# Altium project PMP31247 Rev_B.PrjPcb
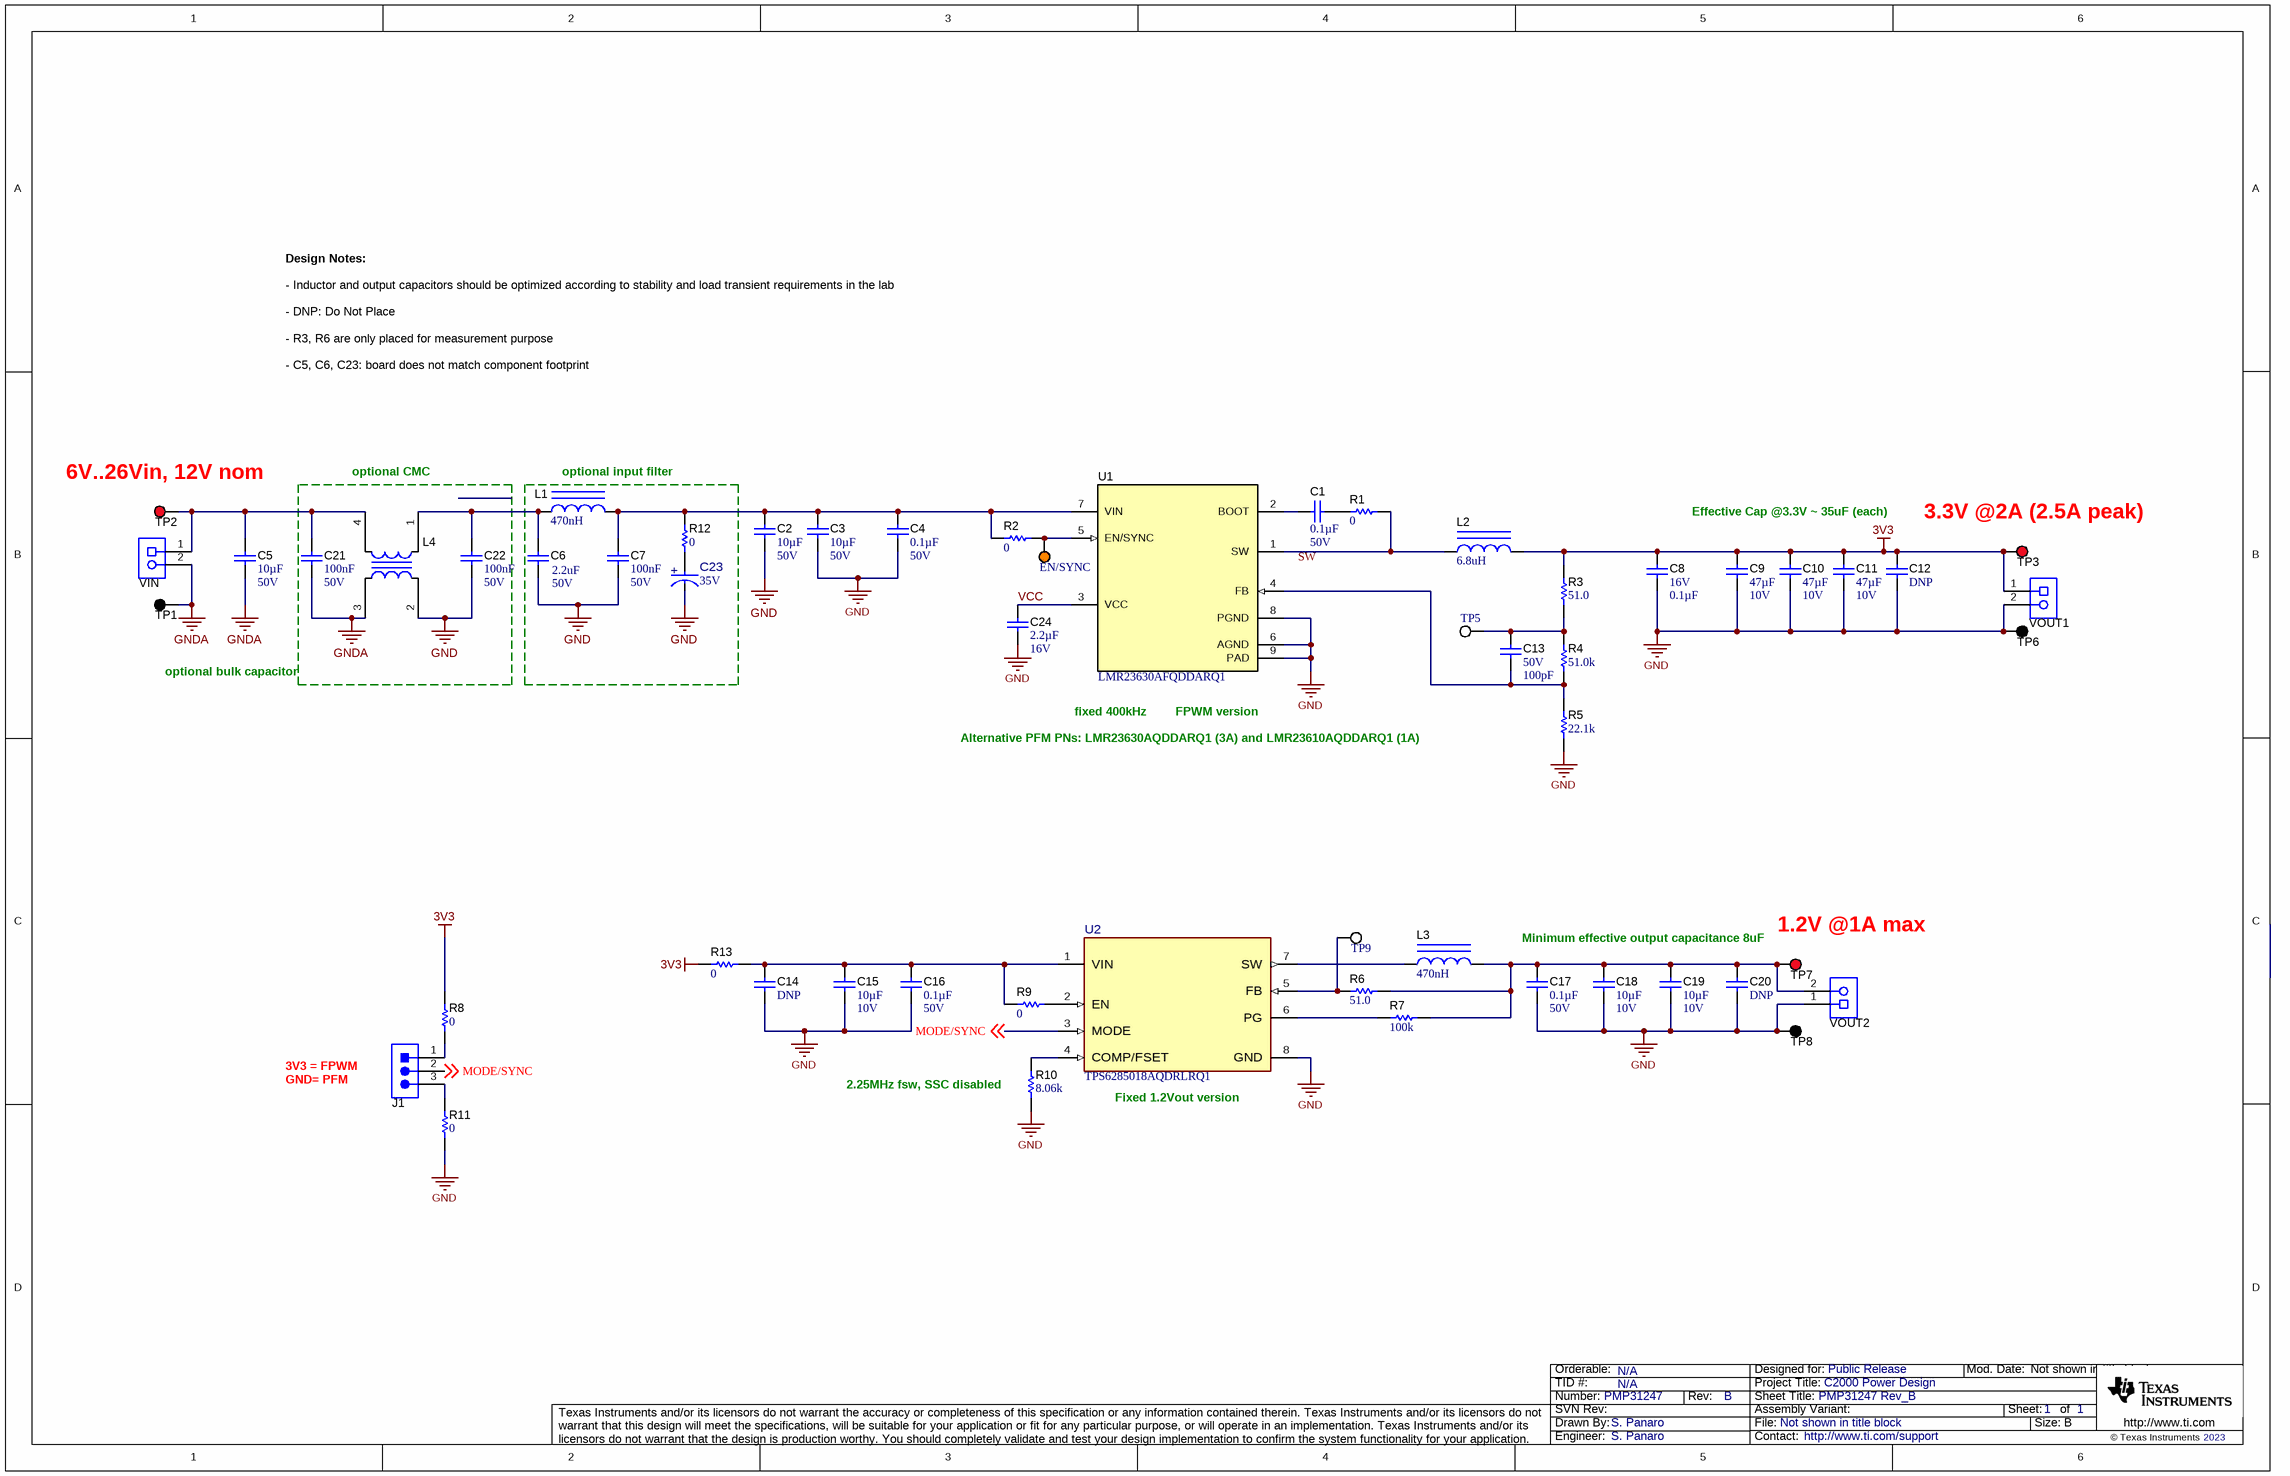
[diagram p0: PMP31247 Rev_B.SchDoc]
TID: N/A; TechSupport: http://www.ti.com/support; SCH_Rev: B; PRJ_Title: C2000 Power Design; PRJ_Number: PMP31247; PRJ_Engineer: S. Panaro; PRJ_Customer: Public Release; Orderable: N/A; CopyrightYear: 2023
1 sheet, 56 parts. Net scope: global (net labels, ports and power ports of the same name join across sheets).
Board file: PMP31247 Rev_B.PcbDoc

## Sheet PMP31247 Rev_B.SchDoc: PMP31247 Rev_B
size 431 x 279 mm; Date: Not shown in title block; ApprovedBy: Not shown in title block; CheckedBy: Not shown in title block; Author: Not shown in title block; CompanyName: Not shown in title block; DrawnBy: S. Panaro; Engineer: S. Panaro; Organization: Not shown in title block; Address1: Not shown in title block; Address2: Not shown in title block; Address3: Not shown in title block; Address4: Not shown in title block; DocumentNumber: 1; Revision: Use project parameter SCH_Rev; SheetNumber: 1; SheetTotal: 1; PageSetup: Record=PageOptions¦CenterHorizontal=True¦CenterVertical=True¦PrintScale=1.00¦XCorrection=1.00¦YCorrection=1.00¦PrintKind=0¦BorderSize=5000000¦LeftOffset=0¦BottomOffset=0¦Orientation=2¦PaperLength=1000¦PaperWidth=1000¦Scale=100¦PaperSource=15¦PrintQuality=600¦MediaType=1¦DitherType=10¦PaperKind=Letter¦PrintScaleMode=1; EVM_orderable: N/A

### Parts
C1  ValueDisplayed: 0.1µF  VDC_V: 50V  [0402]  (hidden comment: CGA2B3X7R1H104K050BD)
C2  ValueDisplayed: 10µF  VDC_V: 50V  [1206]  (hidden comment: CGA5L1X7R1H106K160AE)
C3  ValueDisplayed: 10µF  VDC_V: 50V  [1206]  (hidden comment: CGA5L1X7R1H106K160AE)
C4  ValueDisplayed: 0.1µF  VDC_V: 50V  [0402]  (hidden comment: CGA2B3X7R1H104K050BD)
C5  ValueDisplayed: 10µF  VDC_V: 50V  [1206]  (hidden comment: CGA5L1X7R1H106K160AE)
C6  VDC_V: 50V  ValueDisplayed: 2.2uF  [1206_180]  (hidden comment: GCM31CR71H225KA55L)
C7  Cap_F: 100nF  VDC_V: 50V  [0603]  (hidden comment: C0603C104K5RACAUTO)
C8  VDC_V: 16V  ValueDisplayed: 0.1µF  [0402]  (hidden comment: GCM155R71C104JA55D)
C9  Cap_F: 47µF  VDC_V: 10V  [1210_270]  (hidden comment: GRM32ED71A476ME15L)
C10  Cap_F: 47µF  VDC_V: 10V  [1210_270]  (hidden comment: GRM32ED71A476ME15L)
C11  Cap_F: 47µF  VDC_V: 10V  [1210_270]  (hidden comment: GRM32ED71A476ME15L)
C12  Cap_F: DNP  [1210_270]  (hidden comment: GRM32ED71A476ME15L)
C13  VDC_V: 50V  ValueDisplayed: 100pF  [0603]  (hidden comment: 06035A101JAT2A)
C14  Cap_F: DNP  [0603]  (hidden comment: GRM188Z71A106MA73D)
C15  Cap_F: 10µF  VDC_V: 10V  [0603]  (hidden comment: GRM188Z71A106MA73D)
C16  ValueDisplayed: 0.1µF  VDC_V: 50V  [0402]  (hidden comment: CGA2B3X7R1H104K050BD)
C17  ValueDisplayed: 0.1µF  VDC_V: 50V  [0402]  (hidden comment: CGA2B3X7R1H104K050BD)
C18  Cap_F: 10µF  VDC_V: 10V  [0603]  (hidden comment: GRM188Z71A106MA73D)
C19  Cap_F: 10µF  VDC_V: 10V  [0603]  (hidden comment: GRM188Z71A106MA73D)
C20  Cap_F: DNP  [0603]  (hidden comment: GRM188Z71A106MA73D)
C21  Cap_F: 100nF  VDC_V: 50V  [0603]  (hidden comment: C0603C104K5RACAUTO)
C22  Cap_F: 100nF  VDC_V: 50V  [0603]  (hidden comment: C0603C104K5RACAUTO)
C23  VDC_V: 35V  [FP-EEH-ZK1V101XP_RADIAL-MFG]  (hidden comment: EEH-ZK1V390UR)
C24  Cap_F: 2.2µF  VDC_V: 16V  [0603]  (hidden comment: EMK107BB7225KA-T)
EN/SYNC  5003  [Keystone5003]  (value not drawn)
J1  61300311121  [WURTH_61300311121]  (value not drawn)
L1  ValueDisplayed: 470nH  [SRN2010TA]  (hidden comment: SRN2010TA-R47Y)
L2  ValueDisplayed: 6.8uH  [WE-PD_1260]  (hidden comment: 744771006)
L3  ValueDisplayed: 470nH  [DFE252012P]  (hidden comment: DFE252012PD-R47M)
L4  ACM9070-701-2PL-TL01  [TDK_ACM9070]  (value not drawn)
R1  ValueDisplayed: 0  [0402]  (hidden comment: CRCW04020000Z0ED)
R2  ValueDisplayed: 0  [0603]  (hidden comment: CRCW06030000Z0EA)
R3  ValueDisplayed: 51.0  [0603]  (hidden comment: RC0603FR-0751RL)
R4  ValueDisplayed: 51.0k  [0603]  (hidden comment: RC0603FR-0751KL)
R5  ValueDisplayed: 22.1k  [0603]  (hidden comment: CRCW060322K1FKEA)
R6  ValueDisplayed: 51.0  [0603]  (hidden comment: RC0603FR-0751RL)
R7  ValueDisplayed: 100k  [0603]  (hidden comment: CRCW0603100KFKEA)
R8  ValueDisplayed: 0  [0603]  (hidden comment: CRCW06030000Z0EA)
R9  ValueDisplayed: 0  [0603]  (hidden comment: CRCW06030000Z0EA)
R10  ValueDisplayed: 8.06k  [0603]  (hidden comment: CRCW06038K06FKEA)
R11  ValueDisplayed: 0  [0603]  (hidden comment: CRCW06030000Z0EA)
R12  ValueDisplayed: 0  [0603]  (hidden comment: CRCW06030000Z0EA)
R13  ValueDisplayed: 0  [0603]  (hidden comment: CRCW06030000Z0EA)
TP1  5011  [Keystone5011]  (value not drawn)
TP2  5010  [Keystone5010]  (value not drawn)
TP3  5010  [Keystone5010]  (value not drawn)
TP5  5012  [Keystone5012]  (value not drawn)
TP6  5011  [Keystone5011]  (value not drawn)
TP7  5010  [Keystone5010]  (value not drawn)
TP8  5011  [Keystone5011]  (value not drawn)
TP9  5012  [Keystone5012]  (value not drawn)
U1  LMR23630AFQDDARQ1  [DDA0008E_L]
U2  TPS6285018AQDRLRQ1  [DRL0008A-MFG]
VIN  ED120/2DS  [On-Shore_ED120_2DS]  (value not drawn)
VOUT1  ED120/2DS  [On-Shore_ED120_2DS]  (value not drawn)
VOUT2  ED120/2DS  [On-Shore_ED120_2DS]  (value not drawn)

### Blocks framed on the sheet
optional CMC: C21 C22 L4
optional input filter: C6 C7 C23 L1 R12

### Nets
3V3: C8.1 C9.1 C10.1 C11.1 C12.1 L2.2 R3.2 R8.2 R13.1 TP3.1 VOUT1.1
GND: C2.2 C3.2 C4.2 C6.2 C7.2 C8.2 C9.2 C10.2 C11.2 C12.2 C14.2 C15.2 C16.2 C17.2 C18.2 C19.2 C20.2 C22.2 C23.1(CATHODE) C24.2 L4.2 R5.1 R10.1 R11.1 TP6.1 TP8.1 U1.6(AGND) U1.8(PGND) U1.9(PAD) U2.8(GND) VOUT1.2 VOUT2.1
GNDA: C5.2 C21.2 L4.3 TP1.1 VIN.2
MODE/SYNC: J1.2 U2.3(MODE) ; off-sheet MODE/SYNC
VCC: C24.1 U1.3(VCC)
NetC1_1: C1.1 U1.2(BOOT)
NetC1_2: C1.2 R1.2
NetC2_1: C2.1 C3.1 C4.1 C7.1 L1.2 R2.1 R12.2 U1.7(VIN)
NetC5_1: C5.1 C21.1 L4.4 TP2.1 VIN.1
NetC6_1: C6.1 C22.1 L1.1 L4.1
NetC13_1: C13.1 R3.1 R4.2 TP5.1
NetC13_2: C13.2 R4.1 R5.2 U1.4(FB)
NetC14_1: C14.1 C15.1 C16.1 R9.1 R13.2 U2.1(VIN)
NetC17_1: C17.1 C18.1 C19.1 C20.1 L3.2 R6.1 R7.2 TP7.1 VOUT2.2
NetC23_2: C23.2(ANODE) R12.1
NetEN/SYNC_1: EN/SYNC.1 R2.2 U1.5(EN/SYNC)
NetJ1_1: J1.1 R8.1
NetJ1_3: J1.3 R11.2
NetL2_1: L2.1 R1.1 U1.1(SW)
NetL3_1: L3.1 U2.7(SW)
NetR6_2: R6.2 TP9.1 U2.5(FB)
NetR7_1: R7.1 U2.6(PG)
NetR9_2: R9.2 U2.2(EN)
NetR10_2: R10.2 U2.4(COMP/FSET)

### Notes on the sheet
- Design Notes:
- - Inductor and output capacitors should be optimized according to stability and load transient requirements in the lab
- - DNP: Do Not Place
- - R3, R6 are only placed for measurement purpose
- - C5, C6, C23: board does not match component footprint
- (near TP2) 6V..26Vin, 12V nom
- Effective Cap @3.3V ~ 35uF (each)
- (near TP3) 3.3V @2A (2.5A peak)
- optional bulk capacitor
- (near U1) fixed 400kHz
- Alternative PFM PNs: LMR23630AQDDARQ1 (3A) and LMR23610AQDDARQ1 (1A)
- (near U1) FPWM version
- Minimum effective output capacitance 8uF
- (near TP7) 1.2V @1A max
- (near J1) 3V3 = FPWM                                                                                                             GND= PFM
- (near R10) 2.25MHz fsw, SSC disabled
- (near U2) Fixed 1.2Vout version
- Labels drawn without touching a wire or pin: SW

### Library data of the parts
C1 C4 C16 C17 = CMP-0084548-1: CAP, CERM, 0.1 µF, 50 V,+/- 10%, X7R, AEC-Q200 Grade 1, 0402; Manufacturer: TDK; SizeZ_mm: 0.6; TaMax_C: 125°C; Cap_F: 100nF; Polarized: N; SizeX_mm: 1; Value: 0.1uF; AEC Category: Q200; TaMin_C: -55°C; SizeArea_mm2: 0.5; SizeAreaWB_mm2: 3; U/M: EA; AEC Qualified: Y
C2 C3 C5 = CMP-0860898-1: CAP, CERM, 10 µF, 50 V,+/- 10%, X7R, AEC-Q200 Grade 1, 1206; Manufacturer: TDK; SizeY_mm: 1.6; AEC Category: Q200; U/M: EA; Polarized: N; TaMin_C: -55°C; TaMax_C: 125°C; SizeX_mm: 3.2; AEC Qualified: Y; SizeZ_mm: 1.35; Value: 10uF; SizeArea_mm2: 5.12; SizeAreaWB_mm2: 10.92; AEC Grade: 1
C6 = CMP-0008814-2: CAP, CERM, 2.2 uF, 50 V, +/- 10%, X7R, AEC-Q200 Grade 1, 1206; Manufacturer: MuRata; TaMin_C: -55°C; Polarized: N; SizeAreaWB_mm2: 10.92; Value1: Unknown; U/M: EA; Value: 2.2uF; TaMax_C: 125°C; SizeZ_mm: 1.8; SizeX_mm: 3.2; SizeY_mm: 1.6; Cap_Case: 1206; SizeArea_mm2: 5.12; AEC Qualified: Y; Cap_F: 2.2µF; AEC Grade: 1; AEC Category: Q200
C7 C21 C22 = CMP-0079602-1: CAP, CERM, 0.1 µF, 50 V,+/- 10%, X7R, AEC-Q200 Grade 1, 0603; Manufacturer: Kemet; TaMin_C: -55°C; Polarized: N; SizeAreaWB_mm2: 4.68; U/M: EA; Value: 0.1uF; TaMax_C: 125°C; SizeZ_mm: 1; SizeX_mm: 1.6; SizeY_mm: 0.8; SizeArea_mm2: 1.28; AEC Qualified: Y; AEC Category: Q200; ValueDisplayed: 0.1µF
C8 = CMP-0080702-1: CAP, CERM, 0.1 µF, 16 V,+/- 5%, X7R, AEC-Q200 Grade 1, 0402; Manufacturer: MuRata; Cap_F: 100nF; SizeAreaWB_mm2: 3; SizeArea_mm2: 0.5; AEC Qualified: Y; AEC Category: Q200; Value: 0.1uF; TaMax_C: 125°C; SizeZ_mm: 0.6; AEC Grade: 1; Polarized: N; TaMin_C: -55°C; U/M: EA
C9-C12 = CMP-0086480-2: 47µF ±20% 10V Ceramic Capacitor X7T 1210 (3225 Metric); Manufacturer: Murata; AEC Qualified: No; SizeZ_mm: 2.7mm; TempCo: +22-33%
C13 = CMP-0006763-4: CAP, CERM, 100 pF, 50 V, +/- 5%, C0G/NP0, 0603; Manufacturer: AVX; TaMin_C: -55°C; ESR_ohm: 0.119; Polarized: N; SizeAreaWB_mm2: 4.68; Value1: 0.119 ohm; U/M: EA; Value: 100pF; TaMax_C: 125°C; SizeZ_mm: 1; SizeX_mm: 1.6; SizeY_mm: 0.8; SizeArea_mm2: 1.28; AEC Category: Q200
C14 C20 = CMP-0007497-5: CAP, CERM, 10 uF, 10 V, +/- 20%, X7R, 0603; Manufacturer: MuRata; TaMin_C: -55°C; Polarized: N; SizeAreaWB_mm2: 4.68; Value1: Unknown; U/M: EA; Value: 10uF; TaMax_C: 125°C; SizeZ_mm: 1; SizeX_mm: 1.6; SizeY_mm: 0.8; Value2: 10V; SizeArea_mm2: 1.28; AEC Category: Q200
C15 C18 C19 = CMP-0007497-5: CAP, CERM, 10 uF, 10 V, +/- 20%, X7R, 0603; Manufacturer: MuRata; TaMin_C: -55°C; Polarized: N; SizeAreaWB_mm2: 4.68; Value1: Unknown; U/M: EA; Value: 10uF; TaMax_C: 125°C; SizeZ_mm: 1; SizeX_mm: 1.6; SizeY_mm: 0.8; SizeArea_mm2: 1.28; AEC Category: Q200
C23 = CMP-0097026-1: 39 µF 35 V Aluminum - Polymer Capacitors Radial, Can - SMD 100mOhm 4000 Hrs @ 125°C; Manufacturer: Panasonic; Cap_F: 39µF; AEC Qualified: Yes; Life: 4000Hours; Value: 39µF; Tolerance_%: 20%
C24 = CMP-0007121-4: CAP, CERM, 2.2 uF, 16 V, +/- 10%, X7R, 0603; Manufacturer: Taiyo Yuden; TaMin_C: -55°C; Polarized: N; SizeAreaWB_mm2: 4.68; Value1: Unknown; U/M: EA; Value: 2.2uF; TaMax_C: 125°C; SizeZ_mm: 1; SizeX_mm: 1.6; SizeY_mm: 0.8; SizeArea_mm2: 1.28; AEC Category: Q200
EN/SYNC = CMP-0055140-2: Test Point, Miniature, Orange, TH; Manufacturer: Keystone Electronics; Green_Lifecycle: Active; ContactFinish: Silver; CNHeader: FALSE; CT: TRUE; Green_REACh: Passed
J1 = CMP-0054796-2: Header, 2.54 mm, 3x1, Gold, TH; Manufacturer: Wurth Elektronik; Pitch_mm: 2.54; Green_Lifecycle: Active; Cert_UL: Y; Shrouded: N; Green_REACh: Passed; Gender: Male; Row_Count: 1
L1 = CMP-0056734-1: Inductor, Shielded, Ferrite, 470 nH, 2.35 A, 0.0528 ohm, AEC-Q200 Grade 1, SMD; Manufacturer: Bourns; Isat: 2.7A @ 30% inductance drop; Irms: 2.35A @ 40C rise; Green_Lifecycle: Active; SizeAreaWB_mm2: 7.8; DCR_ohm: 52.8m; Green_REACh: Passed; Value: 470nH; Imax_A: 2.35A; SizeZ_mm: 1; SizeX_mm: 2; SizeY_mm: 1.6; SizeArea_mm2: 3.2; AEC Qualified: Y; AEC Category: Q200
L2 = CMP-0064211-1: Inductor, Shielded Drum Core, Metal Composite, 6.8 uH, 5.6 A, 0.014 ohm, SMD; Manufacturer: Wurth Elektronik; Isat: 6A @ 10% inductance drop; Irms: 5.6A @ 40C rise; Green_Lifecycle: Active; SizeAreaWB_mm2: 196; DCR_ohm: 14m; Green_REACh: Passed; Value: 6.8uH; Imax_A: 5.6A; SizeZ_mm: 6; SizeX_mm: 12; SizeArea_mm2: 144; Ind_H: 6.8µH; AEC Category: Q200
L3 = CMP-0058944-1: Inductor, Shielded, 470 nH, 4.7 A, 0.021 ohm, SMD; Manufacturer: MuRata Toko; Isat: 6.1A @ 30% inductance drop; Irms: 4.7A @ 40C rise; SizeAreaWB_mm2: 10.5; DCR_ohm: 21m; Value: 470nH; Imax_A: 4.7A; SizeZ_mm: 1.2; SizeX_mm: 2.5; SizeY_mm: 2; SizeArea_mm2: 5; AEC Category: Q200
L4 = CMP-0013076-3: Coupled inductor, 5 A, 0.01 ohm, SMD; Manufacturer: TDK; DCR_ohm: 10m
R1 = CMP-0026822-1: RES, 0, 5%, 0.063 W, 0402; Manufacturer: Vishay-Dale; Power_W: 63mW; TempCo: 200 ppm/C; Value_Code: 0000; U/M: EA; Value: 0; EIA_Code: E24; SizeX_mm: 1; SizeY_mm: 0.5; SizeZ_mm: 0.6; Value2: 0.063W; VDC_V: 50V; AEC Category: Q200
R2 R8 R9 R11 R13 = CMP-0025697-2: RES, 0, 5%, 0.1 W, 0603; Manufacturer: Vishay-Dale; Power_W: 100mW; TempCo: 200 ppm/C; Value_Code: 0000; U/M: EA; Value: 0; EIA_Code: E24; SizeX_mm: 1.6; SizeY_mm: 0.8; SizeZ_mm: 1; Value2: 0.1W; SizeArea_mm2: 1.28; VDC_V: 75V; AEC Category: Q200
R3 R6 = CMP-0023169-5: RES, 51.0, 1%, 0.1 W, 0603; Manufacturer: Yageo; Power_W: 100mW; TempCo: 100 ppm/C; Value_Code: 51R0; Value: 51.0; Res_ohm: 51; SizeX_mm: 1.6; SizeY_mm: 0.8; SizeZ_mm: 1; Value2: 0.1W; SizeArea_mm2: 1.28; AEC Qualified: N; VDC_V: 75V; AEC Category: Q200; SizeAreaWB_mm2: 4.68
R4 = CMP-0023167-5: RES, 51.0 k, 1%, 0.1 W, 0603; Manufacturer: Yageo; Power_W: 100mW; TempCo: 100 ppm/C; Value_Code: 51k0; Value: 51.0k; Res_ohm: 51k; SizeX_mm: 1.6; SizeY_mm: 0.8; SizeZ_mm: 1; Value2: 0.1W; SizeArea_mm2: 1.28; AEC Qualified: N; VDC_V: 75V; AEC Category: Q200; SizeAreaWB_mm2: 4.68
R5 = CMP-0022220-4: RES, 22.1 k, 1%, 0.1 W, AEC-Q200 Grade 0, 0603; Manufacturer: Vishay-Dale; Power_W: 100mW; TempCo: 100 ppm/C; Value_Code: 22k1; Value: 22.1k; EIA_Code: E96; SizeX_mm: 1.6; SizeY_mm: 0.8; SizeZ_mm: 1; Value2: 0.1W; SizeArea_mm2: 1.28; AEC Qualified: Y; VDC_V: 75V; AEC Category: Q200; AEC Grade: 0
R7 = CMP-0021990-4: RES, 100 k, 1%, 0.1 W, AEC-Q200 Grade 0, 0603; Manufacturer: Vishay-Dale; Power_W: 100mW; TempCo: 100 ppm/C; Value: 100k; EIA_Code: E96; SizeX_mm: 1.6; SizeY_mm: 0.8; SizeZ_mm: 1; Value2: 0.1W; SizeArea_mm2: 1.28; AEC Qualified: Y; VDC_V: 75V; AEC Category: Q200; AEC Grade: 0
R10 = CMP-0022634-4: RES, 8.06 k, 1%, 0.1 W, AEC-Q200 Grade 0, 0603; Manufacturer: Vishay-Dale; Power_W: 100mW; TempCo: 100 ppm/C; Value_Code: 8k06; Value: 8.06k; EIA_Code: E96; SizeX_mm: 1.6; SizeY_mm: 0.8; SizeZ_mm: 1; Value2: 0.1W; SizeArea_mm2: 1.28; AEC Qualified: Y; VDC_V: 75V; AEC Category: Q200; AEC Grade: 0
R12 = CMP-0025697-4: RES, 0, 5%, 0.1 W, AEC-Q200 Grade 0, 0603; Manufacturer: Vishay-Dale; Power_W: 100mW; TempCo: 200 ppm/C; Value_Code: 0000; Value: 0; EIA_Code: E24; SizeX_mm: 1.6; SizeY_mm: 0.8; SizeZ_mm: 1; Value2: 0.1W; SizeArea_mm2: 1.28; AEC Qualified: Y; VDC_V: 75V; AEC Category: Q200
TP1 TP6 TP8 = CMP-0055148-1: Test Point, Multipurpose, Black, TH; Manufacturer: Keystone; CNHeader: FALSE; Green_Lifecycle: Active; Green_REACh: Passed; ContactFinish: Silver; CT: TRUE
TP2 TP3 TP7 = CMP-0055147-1: Test Point, Multipurpose, Red, TH; Manufacturer: Keystone; CNHeader: FALSE; Green_Lifecycle: Active; Green_REACh: Passed; ContactFinish: Silver; CT: TRUE
TP5 TP9 = CMP-0055149-2: Test Point, Multipurpose, White, TH; Manufacturer: Keystone Electronics; ContactFinish: Silver; CT: TRUE; CNHeader: FALSE; Green_Lifecycle: Active; Green_REACh: Passed
U1 = CMP-0013268-3: SIMPLE SWITCHER, 36V, 3A Synchronous Step-Down Converter, DDA0008E (SOIC-8); Alternate PartNumber: LMR23630AFQDDAQ1; Manufacturer: Texas Instruments; SizeZ_mm: 1.7; SizeX_mm: 5; SizeY_mm: 6.2; SizeArea_mm2: 31; CompType: IC; U/M: EA; SizeAreaWB_mm2: 57.4
U2 = CMP-0092216-2: 1.2V fixed voltage Step-Down Converter; Manufacturer: Texas Instruments; Standoff Height: 0mm; TJmax_C: +150°C; SizeZ_mm: 0.6mm; Switching Frequency: 1.8-4MHz; Min Supply Voltage: 2.7V; CompType: IC; TaMax_C: +125°C; AEC Qualified: Yes; Switching Topology: Buck; Number Of Outputs: 1; AEC Grade: Grade 1; TaMin_C: -40°C; Max Duty Cycle: 100%; AEC Category: Q200; Nominal Supply Current: 17uA; Max Supply Voltage: 6V
VIN VOUT1 VOUT2 = CMP-0074910-1: Terminal Block, 5.08 mm, 2x1, Brass, TH; Manufacturer: On-Shore Technology; Cert_VDE: Y; CNHeader: False; Current_A: 15A; Green_Lifecycle: Not Set; Shrouded: N; Gender: Female; Green_REACh: Incomplete; Voltage_V: 300V; Row_Count: 1; Pitch_mm: 5.08; CT: True

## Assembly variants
001: not fitted C12 C14 C20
